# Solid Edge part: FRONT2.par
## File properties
Author: Andrea Rangi V
Template: Ansi Metric part.par
Last saved by: Andrea Rangi V
Revision: 4
Application: Solid Edge
Accuracy: 0.990
Username: Andrea Rangi V
Face Style: Model Default
Coef. of Thermal Exp: 0.0
Thermal Conductivity: 0.0
Specific Heat: 0.0
Modulus of Elasticity: 0.0
Poisson's Ratio: 0.0
Yield Stress: 0.0
Ultimate Stress: 0.0
Elongation: 0.0
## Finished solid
Body 1: solid body, 38 faces, 108 edges, 72 vertices.
  Faces by surface: plane 38
  Edges by curve: line 108
Bounding box of the edges (mm): 50.000 x 3.000 x 291.000, from (-6.8498, 0, -153.6805) to (43.1502, 3, 137.3195).
Planar faces by outward normal: +x 3, +y 1, +z 9, -x 15, -y 1, -z 9
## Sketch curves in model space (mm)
line (23.1502, 0, 137.3195) -> (13.1502, 0, 137.3195)
line (23.1502, 0, -153.6805) -> (13.1502, 0, -153.6805)
line (-6.8498, 0, 84.8195) -> (-6.8498, 0, 111.3195)
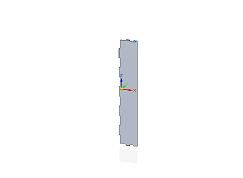
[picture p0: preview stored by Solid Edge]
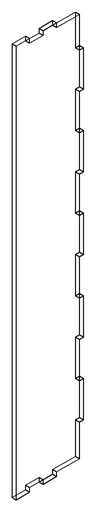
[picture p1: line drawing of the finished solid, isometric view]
